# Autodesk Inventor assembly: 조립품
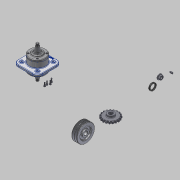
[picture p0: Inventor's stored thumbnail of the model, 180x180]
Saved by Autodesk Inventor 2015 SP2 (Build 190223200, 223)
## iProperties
Created: 2015-07
Part Number: 조립품
Document SubType Name: Assembly
Designer: AMC
Author: AMC
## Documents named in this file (12)
- C:\Users\AMC\Desktop\450735V1004\조립품.iam
- C:\Users\AMC\Desktop\450735V1004\본체.ipt
- C:\Users\AMC\Desktop\450735V1004\2-커버.ipt
- C:\Users\AMC\Desktop\450735V1004\3-축.ipt
- C:\Users\AMC\Desktop\450735V1004\4-V벨트풀리.ipt
- C:\Users\AMC\Desktop\450735V1004\5-체인 스프로킷.ipt
- C:\Users\AMC\Desktop\450735V1004\6-베어링 6206.ipt
- C:\Users\AMC\Desktop\450735V1004\7-부시.ipt
- C:\Users\AMC\Desktop\450735V1004\8-오일실 30x42.ipt
- C:\Users\AMC\Desktop\450735V1004\9-M16-너트.ipt
- C:\Users\AMC\Desktop\450735V1004\10-M6.ipt
- C:\Users\AMC\Desktop\450735V1004\11-키 6x6.ipt
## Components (19 placed, 10 different names)
1. 2-커버:1
2. 3-축:1
3. 4-V벨트풀리:1
4. 5-체인 스프로킷:1
5. 6-베어링 6206:1
6. 7-부시:1
7. 8-8-오일실 30x42:1
8. 9-M16 너트:1
9. 10-M6:1
10. 11-키 6x6:1
11. 6-베어링 6206:2
12. 2-커버:2
13. 10-M6:2
14. 10-M6:3
15. 10-M6:4
16. 10-M6:6
17. 10-M6:7
18. 10-M6:8
19. 10-M6:9
